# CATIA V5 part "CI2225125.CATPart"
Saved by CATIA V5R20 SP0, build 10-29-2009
Part number: CI2225125
Bounding box of the stored display mesh (mm): x -24 to 24, y -18.534 to 159.5, z -34.099 to 26.514
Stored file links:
  C:\Users\Raffaele\Desktop\3D X SITO CF\BOLEX\19-INCLINED ASSEMBLY REF_CI\CI2225125.CATPart
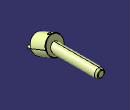
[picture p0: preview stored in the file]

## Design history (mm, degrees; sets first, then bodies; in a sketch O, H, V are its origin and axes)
Set1
  DatumSurface1 to DatumSurface16 "MANIFOLD_SOLID_BREP #389"
  DatumSurface17 to DatumSurface39 "MANIFOLD_SOLID_BREP #1134"
Body1 (main body)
